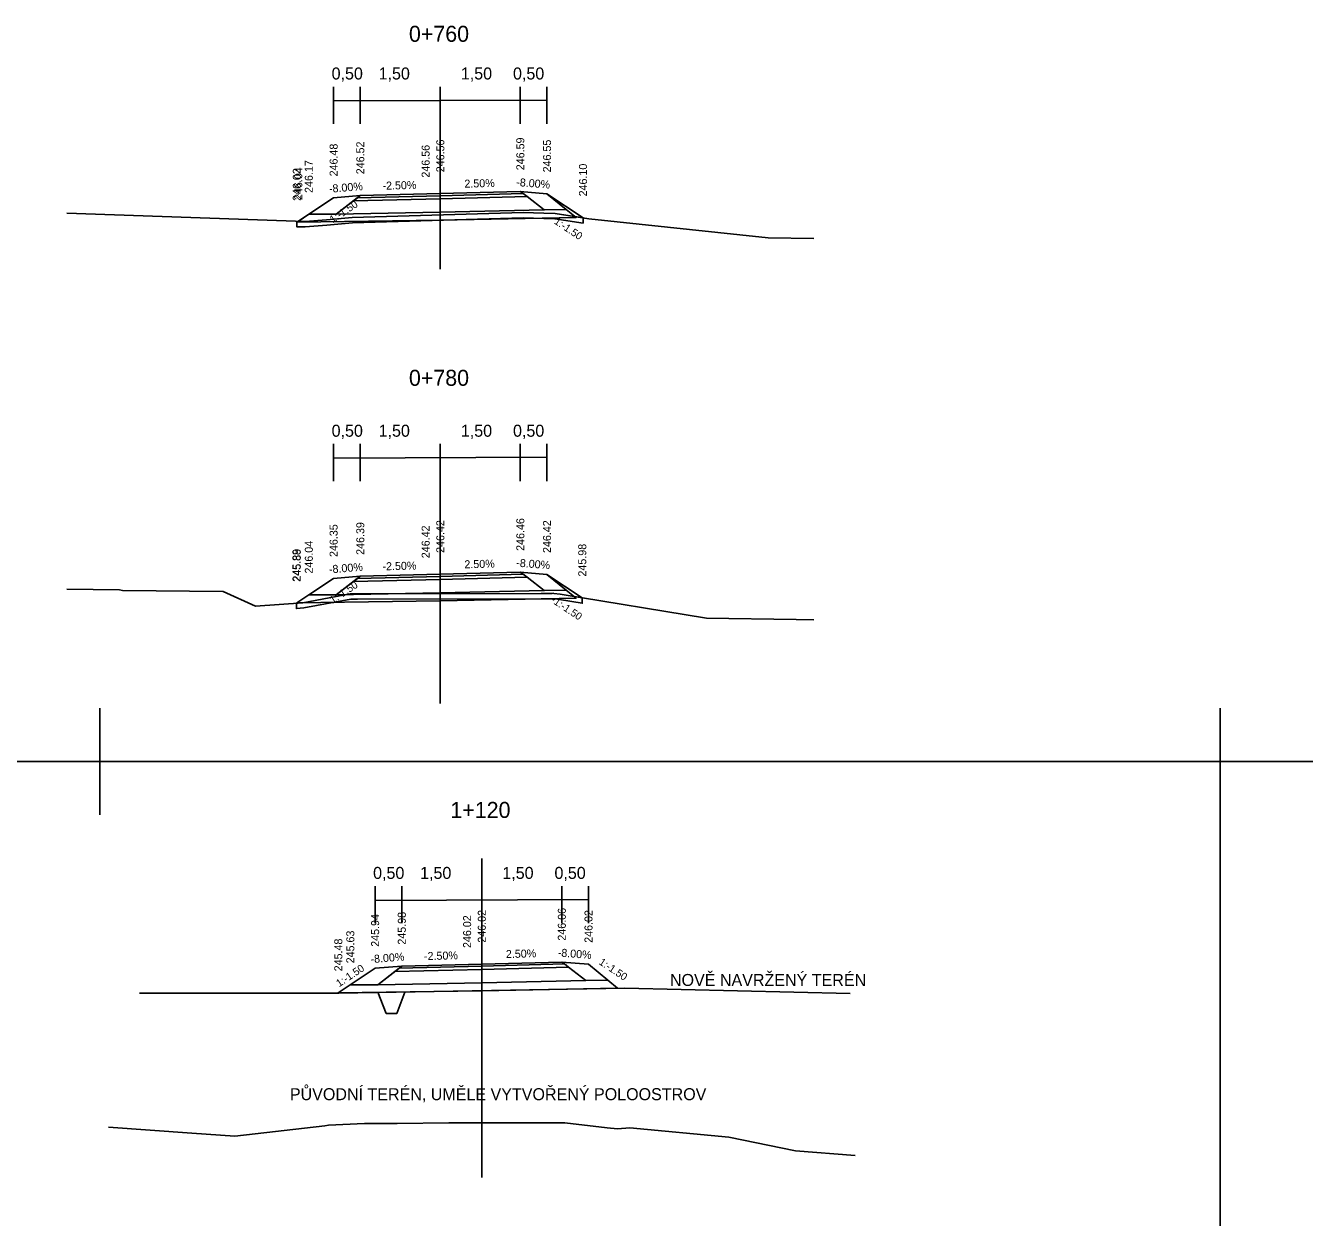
# Model space of a CAD drawing. Extents: x -552501 to -552394, y -1029983 to -1029892.
# Drawn here: x -552438.15 to -552414.17, y -1029961.29 to -1029938.96 of the extents above; entities that cross this region are included whole.
import ezdxf

# ---------------------------------------------------------------- set-up
doc = ezdxf.new("R2010")
doc.units = 0
for name, color, linetype in [('1', 7, 'Continuous'), ('16', 7, 'Continuous'), ('60', 7, 'Continuous'), ('9', 7, 'Continuous'), ('FORMATY', 7, 'Continuous'), ('Implicitní', 7, 'Continuous'), ('rámeček', 7, 'Continuous')]:
    doc.layers.add(name, color=color, linetype=linetype)

msp = doc.modelspace()

# ---------------------------------------------------------------- linework, layer by layer
for p, q in [((-552432.273, -1029957.092), (-552436.009, -1029957.092)), ((-552431.39, -1029957.474), (-552431.54, -1029957.074)), ((-552431.19, -1029957.474), (-552431.04, -1029957.074)), ((-552431.39, -1029957.474), (-552431.19, -1029957.474))]:
    msp.add_line(p, q)
for points in [[(-552433.062, -1029942.648), (-552433.035, -1029942.631), (-552432.837, -1029942.498), (-552432.372, -1029942.188), (-552431.872, -1029942.148), (-552430.372, -1029942.111), (-552428.872, -1029942.073), (-552428.372, -1029942.113), (-552427.697, -1029942.563)], [(-552437.372, -1029942.478), (-552432.908, -1029942.635), (-552432.505, -1029942.601), (-552432.023, -1029942.561), (-552428.817, -1029942.462), (-552428.431, -1029942.478), (-552428.22, -1029942.48), (-552427.59, -1029942.58), (-552424.227, -1029942.939), (-552423.372, -1029942.952)], [(-552433.068, -1029949.785), (-552433.062, -1029949.78), (-552432.837, -1029949.63), (-552432.372, -1029949.32), (-552431.872, -1029949.28), (-552430.372, -1029949.243), (-552428.872, -1029949.205), (-552428.372, -1029949.245), (-552427.711, -1029949.686)], [(-552437.372, -1029949.525), (-552436.386, -1029949.533), (-552436.329, -1029949.548), (-552434.445, -1029949.568), (-552433.834, -1029949.843), (-552432.946, -1029949.776), (-552432.061, -1029949.612), (-552432.003, -1029949.612), (-552431.996, -1029949.611), (-552431.924, -1029949.612), (-552428.481, -1029949.603), (-552428.278, -1029949.604), (-552428.247, -1029949.6), (-552428.243, -1029949.603), (-552428.241, -1029949.602), (-552428.123, -1029949.619), (-552425.385, -1029950.063), (-552423.7, -1029950.093), (-552423.372, -1029950.099)], [(-552432.273, -1029957.092), (-552426.916, -1029957.002), (-552422.69, -1029957.099)], [(-552436.594, -1029959.601), (-552435.031, -1029959.714), (-552434.222, -1029959.774), (-552432.534, -1029959.578), (-552432.469, -1029959.569), (-552431.79, -1029959.536), (-552431.182, -1029959.534), (-552430.211, -1029959.523), (-552428.166, -1029959.524), (-552428.038, -1029959.525), (-552427.241, -1029959.614), (-552427.049, -1029959.634), (-552426.818, -1029959.615), (-552424.964, -1029959.792), (-552423.716, -1029960.047), (-552422.594, -1029960.132)]]:
    msp.add_lwpolyline(points)
for points in [[(-552431.872, -1029942.148), (-552432.372, -1029942.188), (-552432.837, -1029942.498), (-552432.322, -1029942.498)], [(-552432.322, -1029942.498), (-552432, -1029942.248), (-552430.372, -1029942.211), (-552428.744, -1029942.167), (-552428.422, -1029942.417), (-552430.372, -1029942.461)], [(-552430.372, -1029942.151), (-552431.923, -1029942.188), (-552432, -1029942.248), (-552430.372, -1029942.211), (-552428.744, -1029942.167), (-552428.821, -1029942.107), (-552430.372, -1029942.151), (-552428.821, -1029942.107), (-552428.872, -1029942.073), (-552430.372, -1029942.111), (-552431.872, -1029942.148), (-552431.923, -1029942.188)], [(-552432, -1029942.248), (-552431.923, -1029942.188), (-552430.372, -1029942.151), (-552428.821, -1029942.107), (-552428.744, -1029942.167), (-552430.372, -1029942.211)], [(-552428.872, -1029942.073), (-552428.372, -1029942.113), (-552428.011, -1029942.411), (-552428.422, -1029942.417), (-552428.744, -1029942.167), (-552428.821, -1029942.107)], [(-552433.062, -1029942.648), (-552432.837, -1029942.498), (-552432.322, -1029942.498), (-552430.372, -1029942.461), (-552428.422, -1029942.417), (-552428.011, -1029942.411), (-552427.826, -1029942.561), (-552430.372, -1029942.611)], [(-552433.062, -1029942.63), (-552432.908, -1029942.635), (-552432.505, -1029942.601), (-552432.023, -1029942.561), (-552428.817, -1029942.462), (-552428.431, -1029942.478), (-552428.22, -1029942.48), (-552427.697, -1029942.563), (-552427.697, -1029942.664), (-552428.228, -1029942.58), (-552428.433, -1029942.578), (-552428.818, -1029942.562), (-552432.017, -1029942.661), (-552432.497, -1029942.7), (-552432.906, -1029942.735), (-552433.062, -1029942.73)], [(-552431.872, -1029949.28), (-552432.372, -1029949.32), (-552432.837, -1029949.63), (-552432.322, -1029949.63)], [(-552432.322, -1029949.63), (-552432, -1029949.38), (-552430.372, -1029949.343), (-552428.744, -1029949.299), (-552428.422, -1029949.549), (-552430.372, -1029949.593)], [(-552430.372, -1029949.283), (-552431.923, -1029949.32), (-552432, -1029949.38), (-552430.372, -1029949.343), (-552428.744, -1029949.299), (-552428.821, -1029949.239), (-552430.372, -1029949.283), (-552428.821, -1029949.239), (-552428.872, -1029949.205), (-552430.372, -1029949.243), (-552431.872, -1029949.28), (-552431.923, -1029949.32)], [(-552432, -1029949.38), (-552431.923, -1029949.32), (-552430.372, -1029949.283), (-552428.821, -1029949.239), (-552428.744, -1029949.299), (-552430.372, -1029949.343)], [(-552428.872, -1029949.205), (-552428.372, -1029949.245), (-552428.011, -1029949.543), (-552428.422, -1029949.549), (-552428.744, -1029949.299), (-552428.821, -1029949.239)], [(-552433.068, -1029949.785), (-552432.946, -1029949.776), (-552432.061, -1029949.612), (-552432.003, -1029949.612), (-552431.996, -1029949.611), (-552431.924, -1029949.612), (-552428.481, -1029949.603), (-552428.278, -1029949.604), (-552428.247, -1029949.6), (-552428.243, -1029949.603), (-552428.241, -1029949.602), (-552428.123, -1029949.619), (-552427.711, -1029949.686), (-552427.711, -1029949.787), (-552428.138, -1029949.718), (-552428.222, -1029949.706), (-552428.254, -1029949.724), (-552428.278, -1029949.704), (-552428.273, -1029949.704), (-552428.482, -1029949.703), (-552431.925, -1029949.712), (-552431.989, -1029949.711), (-552431.996, -1029949.712), (-552432.051, -1029949.712), (-552432.933, -1029949.875), (-552433.068, -1029949.885)], [(-552433.062, -1029949.78), (-552432.837, -1029949.63), (-552432.322, -1029949.63), (-552430.372, -1029949.593), (-552428.422, -1029949.549), (-552428.011, -1029949.543), (-552427.826, -1029949.693), (-552430.372, -1029949.743)], [(-552431.094, -1029956.584), (-552431.594, -1029956.624), (-552432.059, -1029956.934), (-552431.545, -1029956.934)], [(-552431.545, -1029956.934), (-552431.223, -1029956.684), (-552429.595, -1029956.647), (-552427.966, -1029956.603), (-552427.644, -1029956.853), (-552429.595, -1029956.897)], [(-552429.595, -1029956.587), (-552431.145, -1029956.624), (-552431.223, -1029956.684), (-552429.595, -1029956.647), (-552427.966, -1029956.603), (-552428.043, -1029956.543), (-552429.595, -1029956.587), (-552428.043, -1029956.543), (-552428.094, -1029956.509), (-552429.594, -1029956.547), (-552431.094, -1029956.584), (-552431.145, -1029956.624)], [(-552431.223, -1029956.684), (-552431.145, -1029956.624), (-552429.595, -1029956.587), (-552428.043, -1029956.543), (-552427.966, -1029956.603), (-552429.595, -1029956.647)], [(-552428.094, -1029956.509), (-552427.594, -1029956.549), (-552427.233, -1029956.847), (-552427.644, -1029956.853), (-552427.966, -1029956.603), (-552428.043, -1029956.543)], [(-552432.284, -1029957.084), (-552432.059, -1029956.934), (-552431.545, -1029956.934), (-552429.595, -1029956.897), (-552427.644, -1029956.853), (-552427.233, -1029956.847), (-552427.048, -1029956.997), (-552429.595, -1029957.047)]]:
    msp.add_lwpolyline(points, close=True)
at = {"layer": '60'}
for p, q in [((-552430.372, -1029940.667), (-552430.372, -1029943.528)), ((-552430.372, -1029947.667), (-552430.372, -1029951.667)), ((-552429.594, -1029954.569), (-552429.594, -1029960.548))]:
    msp.add_line(p, q, dxfattribs=at)
at = {"layer": '9'}
for p, q in [((-552432.372, -1029940.107), (-552432.372, -1029940.804)), ((-552431.872, -1029940.107), (-552431.872, -1029940.804)), ((-552430.372, -1029940.107), (-552430.372, -1029941.607)), ((-552428.872, -1029940.107), (-552428.872, -1029940.804)), ((-552428.372, -1029940.107), (-552428.372, -1029940.804)), ((-552432.372, -1029946.801), (-552432.372, -1029947.498)), ((-552431.872, -1029946.801), (-552431.872, -1029947.498)), ((-552430.372, -1029946.801), (-552430.372, -1029948.301)), ((-552428.872, -1029946.801), (-552428.872, -1029947.498)), ((-552428.372, -1029946.801), (-552428.372, -1029947.498)), ((-552431.595, -1029955.087), (-552431.595, -1029955.784)), ((-552431.095, -1029955.087), (-552431.095, -1029955.784)), ((-552429.595, -1029955.087), (-552429.595, -1029956.587)), ((-552428.095, -1029955.087), (-552428.095, -1029955.784)), ((-552427.595, -1029955.087), (-552427.595, -1029955.784))]:
    msp.add_line(p, q, dxfattribs=at)
at = {"layer": 'FORMATY'}
for p, q in [((-552436.755, -1029951.75), (-552436.755, -1029953.75)), ((-552415.755, -1029951.75), (-552415.755, -1029953.75)), ((-552437.755, -1029952.75), (-552435.755, -1029952.75)), ((-552416.755, -1029952.75), (-552414.755, -1029952.75))]:
    msp.add_line(p, q, dxfattribs=at)
at = {"layer": 'Implicitní'}
for p, q in [((-552432.362, -1029940.374), (-552428.372, -1029940.357)), ((-552432.362, -1029947.068), (-552428.372, -1029947.051)), ((-552431.585, -1029955.354), (-552427.595, -1029955.337))]:
    msp.add_line(p, q, dxfattribs=at)
at = {"layer": 'rámeček'}
for p, q in [((-552436.755, -1029952.25), (-552436.755, -1029952.75)), ((-552415.755, -1029952.25), (-552415.755, -1029952.75)), ((-552499.755, -1029952.75), (-552394.755, -1029952.75)), ((-552499.755, -1029952.75), (-552394.755, -1029952.75)), ((-552499.755, -1029952.75), (-552394.755, -1029952.75)), ((-552415.755, -1029982.45), (-552415.755, -1029952.718))]:
    msp.add_line(p, q, dxfattribs=at)

# ---------------------------------------------------------------- texts
for rotation, p in [(33.6902, (-552432.388, -1029942.668)), (326.3098, (-552428.251, -1029942.663)), (33.6901, (-552432.388, -1029949.8)), (326.3098, (-552428.258, -1029949.79)), (33.6902, (-552432.267, -1029956.983)), (326.3098, (-552427.411, -1029956.541))]:
    msp.add_text('1:-1.50', height=0.14, rotation=rotation).set_placement(p)
at = {"layer": '1'}
for s, p in [('0+760', (-552430.96, -1029939.266)), ('0+780', (-552430.96, -1029945.712)), ('1+120', (-552430.183, -1029953.809))]:
    msp.add_text(s, height=0.3, dxfattribs=at).set_placement(p)
at = {"layer": '16'}
for s, p in [('0,50', (-552432.409, -1029939.972)), ('1,50', (-552431.528, -1029939.972)), ('1,50', (-552429.987, -1029939.972)), ('0,50', (-552429.009, -1029939.972)), ('0,50', (-552432.409, -1029946.666)), ('1,50', (-552431.528, -1029946.666)), ('1,50', (-552429.987, -1029946.666)), ('0,50', (-552429.009, -1029946.666)), ('0,50', (-552431.632, -1029954.952)), ('1,50', (-552430.751, -1029954.952)), ('1,50', (-552429.209, -1029954.952)), ('0,50', (-552428.232, -1029954.952)), ('NOVĚ NAVRŽENÝ TERÉN', (-552426.067, -1029956.958)), ('PŮVODNÍ TERÉN, UMĚLE VYTVOŘENÝ POLOOSTROV', (-552433.192, -1029959.098))]:
    msp.add_text(s, height=0.225, dxfattribs=at).set_placement(p)
for s, rotation, p in [('246.48', 90, (-552432.297, -1029941.788)), ('246.52', 90, (-552431.797, -1029941.748)), ('246.56', 90, (-552430.572, -1029941.811)), ('246.56', 90, (-552430.297, -1029941.711)), ('246.59', 90, (-552428.797, -1029941.673)), ('246.55', 90, (-552428.297, -1029941.713)), ('246.17', 90, (-552432.762, -1029942.098)), ('246.02', 90, (-552432.987, -1029942.248)), ('246.04', 90, (-552432.96, -1029942.231)), ('246.10', 90, (-552427.622, -1029942.163)), ('-8.00%', 4.5739, (-552432.453, -1029942.095)), ('-2.50%', 1.4321, (-552431.454, -1029942.038)), ('2.50%', 1.4321, (-552429.919, -1029942)), ('-8.00%', 355.4261, (-552428.953, -1029941.967)), ('246.42', 90, (-552430.297, -1029948.843)), ('246.46', 90, (-552428.797, -1029948.805)), ('246.42', 90, (-552428.297, -1029948.845)), ('246.35', 90, (-552432.297, -1029948.92)), ('246.39', 90, (-552431.797, -1029948.88)), ('246.42', 90, (-552430.572, -1029948.943)), ('246.04', 90, (-552432.762, -1029949.23)), ('245.98', 90, (-552427.636, -1029949.286)), ('245.88', 90, (-552432.993, -1029949.385)), ('245.89', 90, (-552432.987, -1029949.38)), ('-8.00%', 355.4261, (-552428.953, -1029949.099)), ('-8.00%', 4.5739, (-552432.453, -1029949.227)), ('-2.50%', 1.4321, (-552431.454, -1029949.17)), ('2.50%', 1.4321, (-552429.919, -1029949.132)), ('245.94', 90, (-552431.519, -1029956.224)), ('245.98', 90, (-552431.019, -1029956.184)), ('246.02', 90, (-552429.794, -1029956.247)), ('246.02', 90, (-552429.519, -1029956.147)), ('246.06', 90, (-552428.019, -1029956.109)), ('246.02', 90, (-552427.519, -1029956.149)), ('245.48', 90, (-552432.209, -1029956.684)), ('245.63', 90, (-552431.984, -1029956.534)), ('-8.00%', 4.5739, (-552431.675, -1029956.531)), ('-2.50%', 1.4321, (-552430.676, -1029956.474)), ('2.50%', 1.4321, (-552429.141, -1029956.435)), ('-8.00%', 355.4261, (-552428.175, -1029956.403))]:
    msp.add_text(s, height=0.15, rotation=rotation, dxfattribs=at).set_placement(p)

doc.saveas('drawing.dxf')
